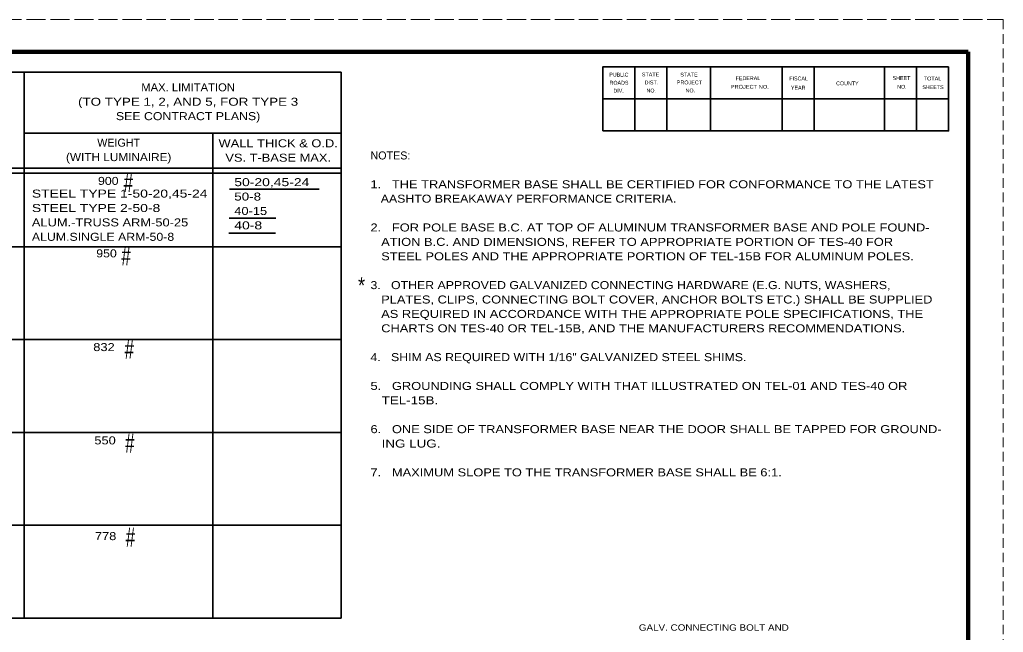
# Model space of a CAD drawing. Extents: x -993 to -313, y 154 to 594.
# Drawn here: x -620.4 to -313.3, y 403.1 to 594.4 of the extents above; entities that cross this region are included whole.
import ezdxf
from ezdxf.enums import TextEntityAlignment as Align

# ---------------------------------------------------------------- set-up
doc = ezdxf.new("R2010")
doc.units = 0
doc.linetypes.add('LONG_DASHED', pattern=[7.5, 6, -1.5])
doc.linetypes.add('MEDIUM_DASHED', pattern=[4.5, 3, -1.5])
doc.layers.add('1', color=7, linetype='Continuous', lineweight=25)
doc.layers.add('61', color=7, linetype='Continuous', lineweight=35)

msp = doc.modelspace()

# ---------------------------------------------------------------- linework, layer by layer
at = {"layer": '1', "linetype": 'MEDIUM_DASHED', "lineweight": 13}
msp.add_line((-313.323, 594.434), (-313.343, 154.414), dxfattribs=at)
at = {"layer": '1', "lineweight": 35}
for p, q in [((-520.085, 578.012), (-957.085, 578.012)), ((-619.085, 578.012), (-619.085, 407.512)), ((-520.085, 578.012), (-520.085, 407.512)), ((-520.085, 559.012), (-619.085, 559.012)), ((-560.085, 559.012), (-560.085, 407.512)), ((-520.085, 548.012), (-957.085, 548.012)), ((-520.085, 546.512), (-957.085, 546.512)), ((-554.883, 541.503), (-526.883, 541.503)), ((-554.995, 532.459), (-540.452, 532.459)), ((-555.106, 527.769), (-540.563, 527.769)), ((-520.085, 523.512), (-957.085, 523.512)), ((-520.085, 494.512), (-957.085, 494.512)), ((-520.085, 465.512), (-957.085, 465.512)), ((-520.085, 436.512), (-957.085, 436.512)), ((-520.085, 407.512), (-957.085, 407.512))]:
    msp.add_line(p, q, dxfattribs=at)
at = {"layer": '61', "linetype": 'LONG_DASHED', "lineweight": 13}
msp.add_line((-993.343, 594.434), (-313.323, 594.434), dxfattribs=at)
at = {"layer": '61', "lineweight": 158}
msp.add_line((-324.303, 584.434), (-324.283, 164.394), dxfattribs=at)
at = {"layer": '61'}
for p, q in [((-428.383, 579.674), (-428.383, 559.674)), ((-418.383, 579.674), (-418.383, 559.674)), ((-404.703, 579.674), (-404.703, 559.674)), ((-382.383, 579.674), (-382.383, 559.674)), ((-372.383, 579.674), (-372.383, 559.674)), ((-350.403, 579.694), (-350.403, 559.694)), ((-340.403, 579.694), (-340.403, 559.694)), ((-330.383, 569.654), (-438.403, 569.674))]:
    msp.add_line(p, q, dxfattribs=at)
at = {"layer": '61', "lineweight": 158}
msp.add_lwpolyline([(-324.303, 584.434), (-963.343, 584.434), (-963.343, 164.414)], dxfattribs=at)
at = {"layer": '61'}
for points in [[(-330.403, 579.694), (-438.383, 579.674), (-438.383, 559.674)], [(-330.403, 579.694), (-330.403, 559.694), (-438.383, 559.674)]]:
    msp.add_lwpolyline(points, dxfattribs=at)

# ---------------------------------------------------------------- texts
at = {"layer": '1'}
for s, width, p in [('MAX. LIMITATION', 1.05, (-567.849, 572.045)), ('(TO TYPE 1, 2, AND 5, FOR TYPE 3', 1.25, (-567.849, 567.545)), ('SEE CONTRACT PLANS)', 1.15, (-567.849, 563.045)), ('WALL THICK & O.D.', 1.2, (-539.724, 554.564)), ('(WITH LUMINAIRE)', 1.1, (-589.529, 550.253)), ('VS. T-BASE MAX.', 1.2, (-539.724, 550.064))]:
    msp.add_text(s, height=2.5, dxfattribs=dict(at, width=width)).set_placement(p, align=Align.CENTER)
msp.add_text('WEIGHT', height=2.5, dxfattribs=at).set_placement((-589.529, 554.753), align=Align.CENTER)
msp.add_text('NOTES:', height=2.5, dxfattribs=at).set_placement((-510.906, 550.769))
for s, height, width, p in [('900', 2.5, 1.15, (-595.981, 542.812)), ('#', 6, 0.65, (-587.955, 540.579)), ('50-20,45-24', 2.5, 1.3, (-553.431, 542.425)), ('1.   THE TRANSFORMER BASE SHALL BE CERTIFIED FOR CONFORMANCE TO THE LATEST', 2.5, 1.2, (-510.906, 541.769)), ('STEEL TYPE 1-50-20,45-24', 2.5, 1.3, (-616.629, 538.852)), ('50-8', 2.5, 1.25, (-553.431, 537.925)), ('   AASHTO BREAKAWAY PERFORMANCE CRITERIA.', 2.5, 1.15, (-510.906, 537.269)), ('STEEL TYPE 2-50-8', 2.5, 1.3, (-616.629, 534.352)), ('40-15', 2.5, 1.2, (-553.431, 533.425)), ('ALUM.-TRUSS ARM-50-25', 2.5, 1.2, (-616.629, 529.852)), ('40-8', 2.5, 1.3, (-553.431, 528.925)), ('2.   FOR POLE BASE B.C. AT TOP OF ALUMINUM TRANSFORMER BASE AND POLE FOUND-', 2.5, 1.2, (-510.906, 528.269)), ('ALUM.SINGLE ARM-50-8', 2.5, 1.15, (-616.629, 525.352)), ('   ATION B.C. AND DIMENSIONS, REFER TO APPROPRIATE PORTION OF TES-40 FOR', 2.5, 1.2, (-510.906, 523.769)), ('950', 2.5, 1.15, (-596.53, 520.176)), ('#', 6, 0.65, (-588.673, 517.732)), ('   STEEL POLES AND THE APPROPRIATE PORTION OF TEL-15B FOR ALUMINUM POLES.', 2.5, 1.2, (-510.906, 519.269)), ('*', 5, 0.85, (-514.797, 508.941)), ('3.   OTHER APPROVED GALVANIZED CONNECTING HARDWARE (E.G. NUTS, WASHERS,', 2.5, 1.15, (-510.906, 510.268)), ('   PLATES, CLIPS, CONNECTING BOLT COVER, ANCHOR BOLTS ETC.) SHALL BE SUPPLIED', 2.5, 1.2, (-510.906, 505.768)), ('   AS REQUIRED IN ACCORDANCE WITH THE APPROPRIATE POLE SPECIFICATIONS, THE', 2.5, 1.2, (-510.906, 501.268)), ('   CHARTS ON TES-40 OR TEL-15B, AND THE MANUFACTURERS RECOMMENDATIONS.', 2.5, 1.2, (-510.906, 496.768)), ('#', 6, 0.65, (-587.66, 488.502)), ('832', 2.5, 1.2, (-597.459, 490.904)), ('4.   SHIM AS REQUIRED WITH 1/16" GALVANIZED STEEL SHIMS.', 2.5, 1.15, (-510.906, 487.768)), ('5.   GROUNDING SHALL COMPLY WITH THAT ILLUSTRATED ON TEL-01 AND TES-40 OR', 2.5, 1.2, (-510.906, 478.768)), ('   TEL-15B.', 2.5, 1.25, (-510.906, 474.268)), ('6.   ONE SIDE OF TRANSFORMER BASE NEAR THE DOOR SHALL BE TAPPED FOR GROUND-', 2.5, 1.2, (-510.906, 465.268)), ('550', 2.5, 1.2, (-597.121, 461.759)), ('#', 6, 0.65, (-587.491, 459.188)), ('   ING LUG.', 2.5, 1.25, (-510.906, 460.768)), ('7.   MAXIMUM SLOPE TO THE TRANSFORMER BASE SHALL BE 6:1.', 2.5, 1.2, (-510.906, 451.768)), ('778', 2.5, 1.2, (-596.952, 431.853)), ('#', 6, 0.65, (-587.322, 429.789)), ('GALV. CONNECTING BOLT AND', 2, 1.15, (-427.129, 403.55))]:
    msp.add_text(s, height=height, dxfattribs=dict(at, width=width)).set_placement(p)
at = {"layer": '61'}
for s, rotation, p in [('PUBLIC', 0.033, (-436.343, 576.654)), ('ROADS', 0.124, (-436.263, 574.134)), ('DIST.', 0.056, (-425.303, 574.214)), ('FEDERAL', 0.007, (-396.883, 575.534)), ('FISCAL', 359.942, (-380.143, 575.474)), ('COUNTY', 0.069, (-365.523, 573.934)), ('SHEET', 0.059, (-347.883, 575.594)), ('DIV.', 359.932, (-435.063, 571.634)), ('YEAR', 0.105, (-379.623, 572.574)), ('SHEETS', 359.959, (-338.603, 572.754))]:
    msp.add_text(s, height=1.201, rotation=rotation, dxfattribs=at).set_placement(p)
for s, rotation, width, p in [('STATE', 0.059, 1.05, (-426.183, 576.714)), ('STATE', 0.059, 1.05, (-414.183, 576.654)), ('PROJECT', 359.908, 1.05, (-415.263, 574.234)), ('TOTAL', 359.926, 1.05, (-338.143, 575.454)), ('NO.', 359.852, 0.95, (-424.723, 571.694)), ('NO.', 0.225, 0.95, (-412.523, 571.694)), ('PROJECT NO.', 359.922, 1.1, (-398.423, 572.874)), ('NO.', 359.852, 0.95, (-346.463, 572.874))]:
    msp.add_text(s, height=1.201, rotation=rotation, dxfattribs=dict(at, width=width)).set_placement(p)

doc.saveas('drawing.dxf')
